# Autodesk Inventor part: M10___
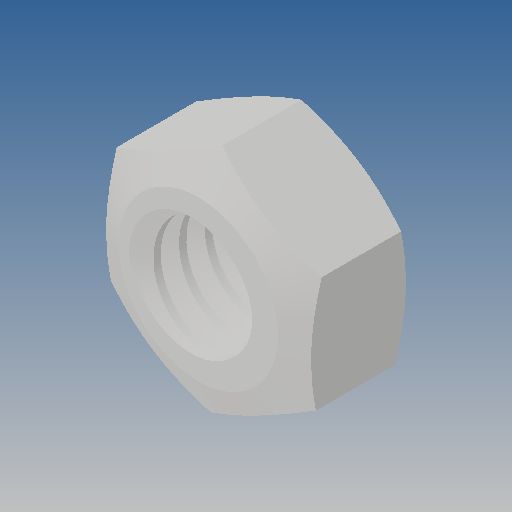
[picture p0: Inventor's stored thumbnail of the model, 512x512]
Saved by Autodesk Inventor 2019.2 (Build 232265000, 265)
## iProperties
Created: 2010-06
Part Number: M10___
Material: Ogólny
Document SubType Name: Modeling
Designer: CADENGINEERING4
Density: 1 g/cm^3
Appearance: Domyślna
Author: CADENGINEERING4
Revision Number: ANY
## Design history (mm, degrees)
feature "NONE"
node "Bryła1"
